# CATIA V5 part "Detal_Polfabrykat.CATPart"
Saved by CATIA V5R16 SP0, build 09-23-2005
Part number: Detal_Polfabrykat
Bounding box of the stored display mesh (mm): x -147.742 to 32.258, y -44.974 to 185.026, z 0 to 70
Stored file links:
  I:\Podręcznik\catia\GeometricModels\Detal_Polfabrykat.CATPart
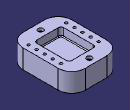
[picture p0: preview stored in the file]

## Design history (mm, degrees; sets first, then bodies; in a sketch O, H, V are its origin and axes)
Body1 "Detal" (main body)
  Sketch1 on xy-plane, origin (0, 0, 0), H (1, 0, 0), V (0, 1, 0)
    line L1 (-97.742, 185.0263) -> (-17.742, 185.0263)
    line L2 (32.258, 135.0263) -> (32.258, 5.0263)
    line L3 (-17.742, -44.9737) -> (-97.742, -44.9737)
    line L4 (-147.742, 5.0263) -> (-147.742, 135.0263)
    point P1 (32.258, 185.0263)
    point P2 (32.258, -44.9737)
    point P3 (-147.742, -44.9737)
    arc A1 centre (-97.742, 135.0263) radius 50 from (-97.742, 185.0263) to (-147.742, 135.0263) ccw
    arc A2 centre (-17.742, 135.0263) radius 50 from (32.258, 135.0263) to (-17.742, 185.0263) ccw
    arc A3 centre (-97.742, 5.0263) radius 50 from (-97.742, -44.9737) to (-147.742, 5.0263) cw
    arc A4 centre (-17.742, 5.0263) radius 50 from (32.258, 5.0263) to (-17.742, -44.9737) cw
    distance P1 P2 = 230
    distance P2 P3 = 180
    radius A1 = 50
    radius A2 = 50
    radius A4 = 50
    radius A3 = 50
    horizontal: L1 H, L3 H
    vertical: L2 V, L4 V
    tangency: A1 L1, A1 L4, A2 L2, A2 L1, A3 L3, A3 L4, A4 L2, A4 L3
    coincidence: L2 P1, L1 P1, L3 P3, L4 P3, L2 P2, L3 P2
  Pad1: profile Sketch1, direction (0, 0, 1), length 70
  Sketch2 on end face of Pad1, origin (0, 0, 70), H (1, 0, 0), V (0, 1, 0)
    point P1 (-107.742, 135.0263)
    line L1 (-97.742, 135.0263) -> (-17.742, 135.0263)
    line L2 (-7.742, 125.0263) -> (-7.742, 15.0263)
    line L3 (-17.742, 5.0263) -> (-97.742, 5.0263)
    line L4 (-107.742, 15.0263) -> (-107.742, 125.0263)
    point P2 (-7.742, 135.0263)
    point P3 (-7.742, 5.0263)
    reference projected line E1 (-17.742, 185.0263) -> (-97.742, 185.0263) from edge [face of Pad1 from Sketch1.L1 | end face of Pad1]
    reference projected line E2 (-147.742, 135.0263) -> (-147.742, 5.0263) from edge [face of Pad1 from Sketch1.L4 | end face of Pad1]
    arc A1 centre (-17.742, 125.0263) radius 10 from (-7.742, 125.0263) to (-17.742, 135.0263) ccw
    arc A2 centre (-97.742, 125.0263) radius 10 from (-97.742, 135.0263) to (-107.742, 125.0263) ccw
    arc A3 centre (-97.742, 15.0263) radius 10 from (-107.742, 15.0263) to (-97.742, 5.0263) ccw
    arc A4 centre (-17.742, 15.0263) radius 10 from (-7.742, 15.0263) to (-17.742, 5.0263) cw
    distance L1 E1 = 50
    distance L4 E2 = 40
    distance P2 P3 = 130
    distance P1 P2 = 100
    horizontal: L1 H, L3 H
    vertical: L2 V, L4 V
    coincidence: L2 P2, L1 P2, L1 P1, L4 P1, L2 P3, L3 P3
    tangency: A1 L2, A1 L1, A2 L1, A2 L4, A3 L4, A3 L3, A4 L2, A4 L3
  Pocket1: profile Sketch2, direction (0, 0, -1), length 30
  Fillet1: radius 3, on end face of Pocket1
  Sketch3 on end face of Pad1, origin (-82.4496, -24.755, 70), H (1, 0, 0), V (0, 1, 0)
    point P1 (24.7076, 4.7813)
    reference projected line E1 (-15.2924, -20.2187) -> (64.7076, -20.2187) from edge [face of Pad1 from Sketch1.L3 | end face of Pad1]
    reference projected line E2 (-65.2924, 159.7813) -> (-65.2924, 29.7813) from edge [face of Pad1 from Sketch1.L4 | end face of Pad1]
    distance P1 E1 = 25
    distance P1 E2 = 90
  Hole1: placed by Sketch3, at (-57.742, -19.9737, 70) direction (0, 0, -1), diameter 15, through (limit type 3), counterbore diameter 20, counterbore depth 10
  Sketch4 on end face of Pad1, origin (-65.3214, 155.2892, 70), H (1, 0, 0), V (0, 1, 0)
    point P1 (7.5794, 4.7371)
    reference projected line E1 (47.5794, 29.7371) -> (-32.4206, 29.7371) from edge [face of Pad1 from Sketch1.L1 | end face of Pad1]
    reference projected line E2 (-82.4206, -20.2629) -> (-82.4206, -150.2629) from edge [face of Pad1 from Sketch1.L4 | end face of Pad1]
    distance P1 E1 = 25
    distance P1 E2 = 90
  Hole2: placed by Sketch4, at (-57.742, 160.0263, 70) direction (0, 0, -1), diameter 15, through (limit type 3), counterbore diameter 20, counterbore depth 10
  Sketch5 on end face of Pad1, origin (-136.2005, 55.5099, 70), H (1, 0, 0), V (0, 1, 0)
    point P1 (8.4585, -50.4836)
    reference projected line E1 (-11.5415, 79.5164) -> (-11.5415, -50.4836) from edge [face of Pad1 from Sketch1.L4 | end face of Pad1]
    reference projected line E2 (38.4585, -100.4836) -> (118.4585, -100.4836) from edge [face of Pad1 from Sketch1.L3 | end face of Pad1]
    distance P1 E1 = 20
    distance P1 E2 = 50
  Hole3: placed by Sketch5, at (-127.742, 5.0263, 70) direction (0, 0, -1), diameter 10, through (limit type 3)
  RectPattern1: of Hole3, direction 1 instances 5, spacing 30, along edge [end face of Pad1 | face of Pocket1 from Sketch2.L4] reversed
  Sketch6 on end face of Pad1, origin (10.3873, 10.494, 70), H (1, 0, 0), V (0, 1, 0)
    point P1 (1.8707, -5.4677)
    reference projected line E1 (21.8707, -5.4677) -> (21.8707, 124.5323) from edge [face of Pad1 from Sketch1.L2 | end face of Pad1]
    reference projected line E2 (-108.1293, -55.4677) -> (-28.1293, -55.4677) from edge [face of Pad1 from Sketch1.L3 | end face of Pad1]
    distance P1 E1 = 20
    distance P1 E2 = 50
  Hole4: placed by Sketch6, at (12.258, 5.0263, 70) direction (0, 0, -1), diameter 10, through (limit type 3)
  RectPattern2: of Hole4, direction 1 instances 5, spacing 30, along edge [end face of Pad1 | face of Pocket1 from Sketch2.L2]
Body2 "Polfabrykat"
  Sketch7 on start face of Pad1, origin (0, 0, 0), H (1, 0, 0), V (0, -1, 0)
    line L1 (-150.129, 49.9737) -> (37.258, 49.9737)
    line L2 (37.258, 49.9737) -> (37.258, -190.0263)
    line L3 (37.258, -190.0263) -> (-150.129, -190.0263)
    line L4 (-150.129, -190.0263) -> (-150.129, 49.9737)
    reference projected line E1 (-17.742, -185.0263) -> (-97.742, -185.0263) from edge [start face of Pad1 | face of Pad1 from Sketch1.L1]
    reference projected line E2 (32.258, -5.0263) -> (32.258, -135.0263) from edge [start face of Pad1 | face of Pad1 from Sketch1.L2]
    length L2 = 240
    distance E1 L3 = 5
    distance E2 L2 = 5
    horizontal: L1 H, L3 H
    vertical: L2 V, L4 V
  Pad2: profile Sketch7, direction (0, 0, 1), length 75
